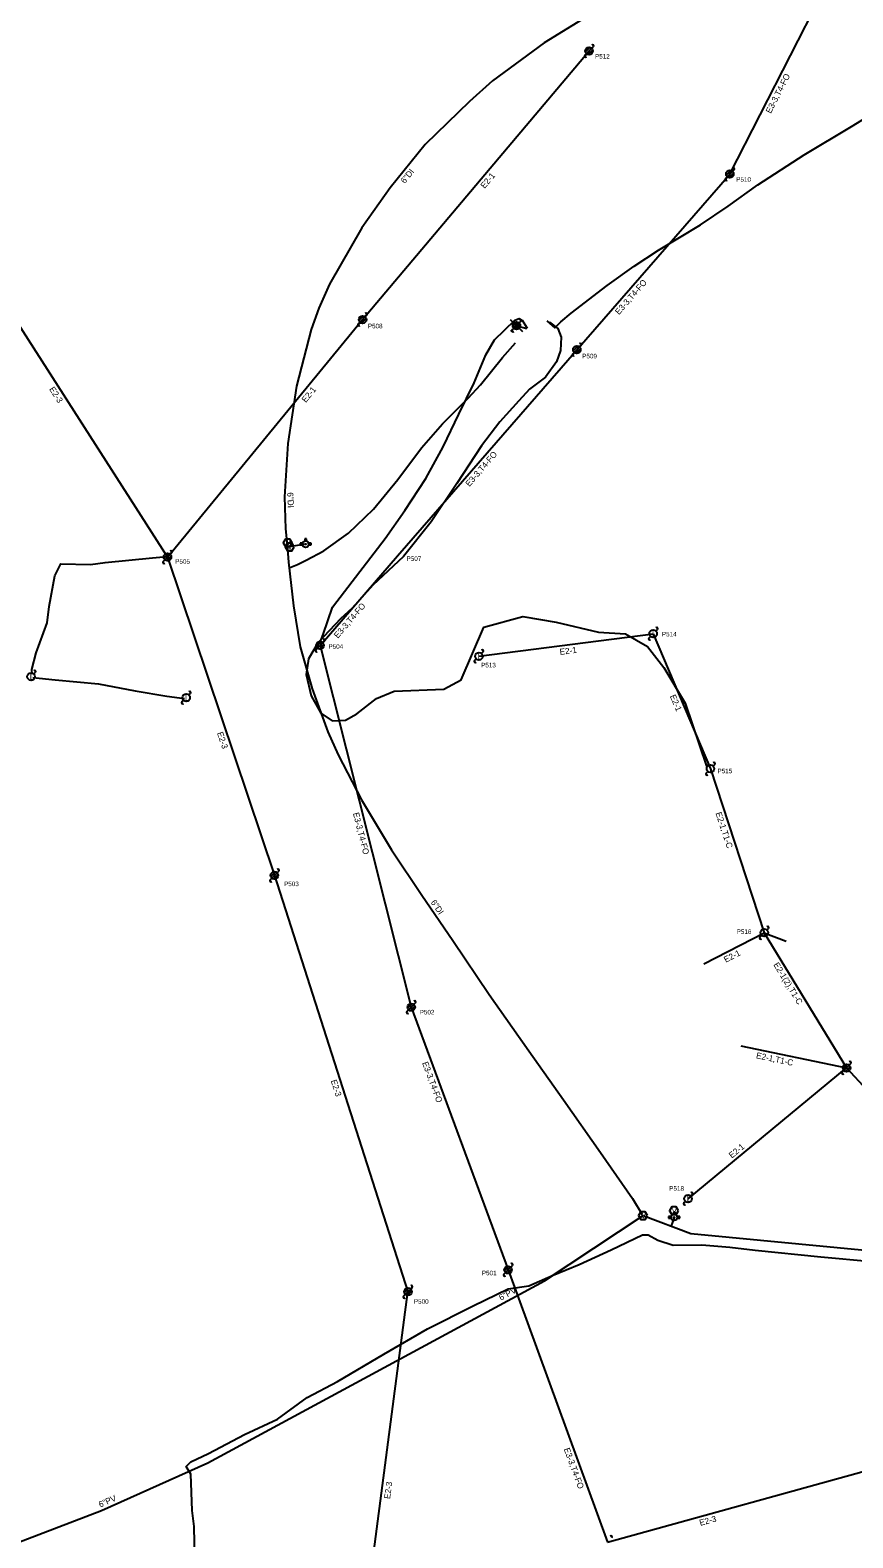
# Model space of a CAD drawing. Extents: x 1741604 to 1825760, y 1164229 to 1194908.
# Drawn here: x 1812735 to 1813275, y 1190349 to 1191338 of the extents above; entities that cross this region are included whole.
import ezdxf

# ---------------------------------------------------------------- set-up
doc = ezdxf.new("R2010")
doc.units = 0
for name, color, linetype in [('RD_EX_SU_Elec', 7, 'Continuous'), ('RD_EX_SU_H2O', 7, 'Continuous'), ('RD_EX_SU_Ovhd', 7, 'Continuous'), ('RD_EX_SU_Pole', 7, 'Continuous'), ('RD_EX_SU_Telecom', 7, 'Continuous'), ('RD_EX_SU_TX_H2O', 7, 'Continuous'), ('RD_EX_SU_TX_Pole', 7, 'Continuous')]:
    doc.layers.add(name, color=color, linetype=linetype)

# ---------------------------------------------------------------- blocks, each defined once
blk = doc.blocks.new('SUE_WV')
at = {"layer": 'RD_EX_SU_H2O'}
blk.add_lwpolyline([(2.89, 0), (1.44, 2.5), (-1.44, 2.5), (-2.89, 0), (-1.44, -2.5), (1.44, -2.5)], close=True, dxfattribs=at)
blk.add_text('V', height=3.75, dxfattribs=at).set_placement((-1.43, -1.88))
blk = doc.blocks.new('SUE_WFH')
at = {"layer": 'RD_EX_SU_H2O'}
for p, q in [((-2.01, 0.6), (-3.65, 0.6)), ((-3.65, 0.6), (-3.65, -0.45)), ((-0.48, 3.38), (-0.48, 2.04)), ((0.57, 3.38), (-0.48, 3.38)), ((0.57, 2.02), (0.57, 3.38)), ((3.7, 0.6), (2.01, 0.6)), ((3.7, -0.45), (3.7, 0.6)), ((-3.65, -0.45), (-2.05, -0.45)), ((2.05, -0.45), (3.7, -0.45))]:
    blk.add_line(p, q, dxfattribs=at)
for radius in [2.1, 0.263]:
    blk.add_circle((0, 0), radius, dxfattribs=at)
for start, end in [(163.3387, 192.31502), (74.24552, 103.21276), (347.68498, 16.6613)]:
    blk.add_arc((0, 0), 2.1, start, end, dxfattribs=at)
blk = doc.blocks.new('SUE_PGP')
at = {"layer": 'RD_EX_SU_Pole'}
for p, q in [((-1.06, 1.06), (-3.89, 3.89)), ((1.02, 1.12), (3.86, 3.96)), ((-1.11, -1.04), (-3.94, -3.87)), ((1.06, -1.06), (3.89, -3.89))]:
    blk.add_line(p, q, dxfattribs=at)
for points in [[(0, -2.12), (2.12, 0), (0, 2.12), (-2.12, 0)], [(0, -0.71), (0.71, 0), (0, 0.71), (-0.71, 0)]]:
    blk.add_lwpolyline(points, close=True, dxfattribs=at)
blk = doc.blocks.new('SUE_PP')
at = {"layer": 'RD_EX_SU_Pole'}
for p, q in [((-2.41, -0.65), (0.65, 2.41)), ((-1.77, -1.77), (1.77, 1.77)), ((-0.65, -2.41), (2.41, 0.65)), ((1.77, 1.77), (2.83, 2.83)), ((-2.83, -2.83), (-1.77, -1.77))]:
    blk.add_line(p, q, dxfattribs=at)
blk.add_circle((0, 0), 2.5, dxfattribs=at)
for centre, start, end in [((2.3, 3.36), 315, 135), ((-2.3, -3.36), 135, 315)]:
    blk.add_arc(centre, 0.75, start, end, dxfattribs=at)

msp = doc.modelspace()

# ---------------------------------------------------------------- linework, layer by layer
at = {"layer": 'RD_EX_SU_Elec'}
msp.add_line((1813054.62, 1191144.08), (1813061.12, 1191142.13), dxfattribs=at)
for points in [[(1813074.17, 1191147.22), (1813079.49, 1191142.73), (1813083.35, 1191146.53), (1813090.24, 1191152.3), (1813113.65, 1191170.54), (1813131.4, 1191183.04), (1813147.43, 1191193.7), (1813174.94, 1191210.3), (1813193.18, 1191222.5), (1813212.55, 1191236.51), (1813242.91, 1191256.26), (1813274.11, 1191274.83), (1813305.14, 1191293.76), (1813336.93, 1191314.29), (1813359.03, 1191328.39), (1813379.8, 1191342.76), (1813412.74, 1191364.15), (1813434.94, 1191378.63), (1813468.04, 1191399.22), (1813497.48, 1191419.37)], [(1812925.66, 1190935.15), (1812925.93, 1190937.58), (1812927.41, 1190941.39), (1812933.54, 1190959.29), (1812946.44, 1190976.3), (1812968.14, 1191004.38), (1812981.01, 1191022.74), (1812994.73, 1191043.72), (1813006.27, 1191064.6), (1813016.36, 1191085.94), (1813026.46, 1191106.6), (1813034.21, 1191124.91), (1813039.85, 1191134.84), (1813053.21, 1191147.79), (1813056.02, 1191148.81), (1813057.96, 1191147.72), (1813061.21, 1191142.37)], [(1812736.46, 1190915.41), (1812736.35, 1190918.55), (1812739.18, 1190929.32), (1812746.36, 1190949.03), (1812747.66, 1190959.89), (1812751.44, 1190980.01), (1812755.26, 1190987.79), (1812774.8, 1190987.36), (1812784.49, 1190988.75), (1812815.44, 1190991.73), (1812825.05, 1190992.69)], [(1812737.08, 1190913.27), (1812751.66, 1190911.7), (1812779.98, 1190909), (1812804.11, 1190904.54), (1812824.79, 1190901.05), (1812836.37, 1190899.52)]]:
    msp.add_lwpolyline(points, dxfattribs=at)
at = {"layer": 'RD_EX_SU_H2O'}
for p, q in [((1812914.82, 1191000.41), (1812903.88, 1190998.72)), ((1813072.65, 1190517.33), (1813137.28, 1190560.13)), ((1813157.74, 1190558.93), (1813155.64, 1190553.29)), ((1812851.86, 1190397.83), (1813072.65, 1190517.33)), ((1812782.06, 1190366.57), (1812851.86, 1190397.83)), ((1812695.37, 1190333.45), (1812782.06, 1190366.57))]:
    msp.add_line(p, q, dxfattribs=at)
for points in [[(1813137.28, 1190560.13), (1813168.69, 1190548.44), (1813548.05, 1190512.01), (1813709.49, 1190513.95), (1813790.71, 1190529.92), (1813879.02, 1190555.32), (1814045.36, 1190620.16), (1814170.98, 1190673.34), (1814340.25, 1190745.39), (1814593.33, 1190851.84), (1815112.4, 1191071.44), (1815429.86, 1191203.06), (1815618.35, 1191283.39), (1815883.49, 1191395.05), (1816374.39, 1191600.1)], [(1813105.92, 1191350.16), (1813072.42, 1191329.64), (1813038.59, 1191304.8), (1813023.51, 1191291.19), (1812994.25, 1191262.94), (1812971.3, 1191234.61), (1812952.71, 1191208.35), (1812931.66, 1191171.39), (1812924.71, 1191155.63), (1812919.62, 1191141.53), (1812910.03, 1191104.46), (1812904.33, 1191066.74), (1812901.98, 1191031.81), (1812902.81, 1191010.72), (1812903.77, 1190999.96), (1812904.72, 1190988.78), (1812907.9, 1190960.34), (1812912.27, 1190933.34), (1812920.22, 1190905.86), (1812930.45, 1190877.55), (1812937.38, 1190862.36), (1812952.67, 1190833.02), (1812972.35, 1190800.03), (1812992.14, 1190770.43), (1813012.42, 1190740.61), (1813036.45, 1190705.28), (1813062.33, 1190668.32), (1813085.13, 1190635.98), (1813109.45, 1190601.5), (1813130.33, 1190571.33), (1813136.74, 1190560.89)], [(1812905.12, 1190985.21), (1812910.61, 1190987.27), (1812916.33, 1190990.09), (1812927.91, 1190996.33), (1812944.09, 1191007.99), (1812960.51, 1191023.77), (1812976.45, 1191043.03), (1812991.91, 1191064), (1813005.62, 1191079.71), (1813022.46, 1191096.52), (1813030.66, 1191105.18), (1813045.15, 1191123.21), (1813053.52, 1191132.79)]]:
    msp.add_lwpolyline(points, dxfattribs=at)
at = {"layer": 'RD_EX_SU_Ovhd'}
for p, q in [((1813194.23, 1191243.55), (1813271.75, 1191395.47)), ((1812953.27, 1191148.1), (1813101.89, 1191324.36)), ((1813093.85, 1191128.3), (1813194.23, 1191243.55)), ((1812690.54, 1191202.47), (1812825.32, 1190992.22)), ((1812825.32, 1190992.22), (1812953.27, 1191148.1)), ((1812976.19, 1190993.08), (1813093.85, 1191128.3)), ((1812825.32, 1190992.22), (1812895.48, 1190783.31)), ((1812925.38, 1190934.22), (1812976.19, 1190993.08)), ((1813029.59, 1190927.16), (1813143.93, 1190941.93)), ((1813143.93, 1190941.93), (1813181.53, 1190853.31)), ((1812925.38, 1190934.22), (1812985.23, 1190696.86)), ((1813181.53, 1190853.31), (1813216.82, 1190745.69)), ((1812895.48, 1190783.31), (1812983.08, 1190510.11)), ((1813177.22, 1190725.31), (1813216.82, 1190745.69)), ((1813216.82, 1190745.69), (1813270.85, 1190657.03)), ((1813216.82, 1190745.69), (1813231.16, 1190740.26)), ((1812985.23, 1190696.86), (1813048.73, 1190524.49)), ((1813201.55, 1190671.56), (1813270.85, 1190657.03)), ((1813166.86, 1190571.19), (1813270.85, 1190657.03)), ((1813270.85, 1190657.03), (1813369.89, 1190548.84)), ((1813048.73, 1190524.49), (1813113.89, 1190345.79)), ((1812956.62, 1190307.89), (1812983.08, 1190510.11)), ((1813113.89, 1190345.79), (1813303.67, 1190398.31))]:
    msp.add_line(p, q, dxfattribs=at)
at = {"layer": 'RD_EX_SU_Pole'}
for p, q in [((1812950.86, 1191147.45), (1812953.92, 1191150.52)), ((1812951.5, 1191146.33), (1812955.04, 1191149.87)), ((1812955.04, 1191149.87), (1812956.1, 1191150.93)), ((1812950.44, 1191145.27), (1812951.5, 1191146.33)), ((1812952.62, 1191145.69), (1812955.69, 1191148.75)), ((1813051.46, 1191141.26), (1813052.52, 1191142.32)), ((1813056.05, 1191145.86), (1813057.11, 1191146.92)), ((1813091.44, 1191127.66), (1813094.5, 1191130.72)), ((1813092.08, 1191126.54), (1813095.62, 1191130.07)), ((1813095.62, 1191130.07), (1813096.68, 1191131.13)), ((1813091.02, 1191125.48), (1813092.08, 1191126.54)), ((1813093.2, 1191125.89), (1813096.26, 1191128.95)), ((1813145.7, 1190943.7), (1813146.76, 1190944.76)), ((1813141.1, 1190939.1), (1813142.16, 1190940.16)), ((1813026.76, 1190924.34), (1813027.82, 1190925.4)), ((1813031.36, 1190928.93), (1813032.42, 1190929.99)), ((1812737.6, 1190915.55), (1812738.66, 1190916.61)), ((1812839.35, 1190901.74), (1812840.41, 1190902.8)), ((1812834.75, 1190897.14), (1812835.82, 1190898.2)), ((1813183.3, 1190855.08), (1813184.36, 1190856.14)), ((1813178.7, 1190850.48), (1813179.76, 1190851.54)), ((1812893.07, 1190782.67), (1812896.13, 1190785.73)), ((1812893.71, 1190781.54), (1812897.25, 1190785.08)), ((1812894.83, 1190780.9), (1812897.9, 1190783.96)), ((1812897.25, 1190785.08), (1812898.31, 1190786.14)), ((1812892.65, 1190780.48), (1812893.71, 1190781.54)), ((1813218.59, 1190747.46), (1813219.65, 1190748.52)), ((1813214, 1190742.86), (1813215.06, 1190743.92)), ((1812982.4, 1190694.03), (1812983.46, 1190695.09)), ((1812982.81, 1190696.21), (1812985.87, 1190699.27)), ((1812983.46, 1190695.09), (1812986.99, 1190698.62)), ((1812984.58, 1190694.44), (1812987.64, 1190697.5)), ((1812986.99, 1190698.62), (1812988.06, 1190699.68)), ((1813268.02, 1190654.2), (1813269.08, 1190655.26)), ((1813268.43, 1190656.38), (1813271.49, 1190659.44)), ((1813269.08, 1190655.26), (1813272.62, 1190658.79)), ((1813270.2, 1190654.61), (1813273.26, 1190657.67)), ((1813272.62, 1190658.79), (1813273.68, 1190659.85)), ((1813164.03, 1190568.36), (1813165.09, 1190569.42)), ((1813168.63, 1190572.95), (1813169.69, 1190574.01)), ((1813046.31, 1190523.84), (1813049.38, 1190526.9)), ((1813050.5, 1190526.26), (1813051.56, 1190527.32)), ((1813045.9, 1190521.66), (1813046.96, 1190522.72)), ((1813046.96, 1190522.72), (1813050.5, 1190526.26)), ((1813048.08, 1190522.07), (1813051.14, 1190525.13)), ((1812980.25, 1190507.28), (1812981.31, 1190508.34)), ((1812980.66, 1190509.47), (1812983.73, 1190512.53)), ((1812981.31, 1190508.34), (1812984.85, 1190511.88)), ((1812982.43, 1190507.7), (1812985.49, 1190510.76)), ((1812984.85, 1190511.88), (1812985.91, 1190512.94))]:
    msp.add_line(p, q, dxfattribs=at)
for centre in [(1812953.27, 1191148.1), (1813054.28, 1191144.09), (1813093.85, 1191128.3), (1813143.93, 1190941.93), (1813029.59, 1190927.16), (1812735.83, 1190913.78), (1812837.58, 1190899.97), (1813181.53, 1190853.31), (1812895.48, 1190783.31), (1813216.82, 1190745.69), (1812985.23, 1190696.86), (1813270.85, 1190657.03), (1813166.86, 1190571.19), (1813048.73, 1190524.49), (1812983.08, 1190510.11)]:
    msp.add_circle(centre, 2.5, dxfattribs=at)
for centre, start, end in [((1812955.57, 1191151.46), 315, 135), ((1812950.97, 1191144.74), 135, 315), ((1813051.99, 1191140.73), 135, 315), ((1813056.58, 1191147.45), 315, 135), ((1813096.15, 1191131.66), 315, 135), ((1813091.55, 1191124.95), 135, 315), ((1813146.23, 1190945.29), 315, 135), ((1813141.63, 1190938.57), 135, 315), ((1813027.29, 1190923.81), 135, 315), ((1813031.89, 1190930.52), 315, 135), ((1812738.13, 1190917.14), 315, 135), ((1812839.88, 1190903.33), 315, 135), ((1812835.29, 1190896.61), 135, 315), ((1813183.83, 1190856.67), 315, 135), ((1813179.23, 1190849.95), 135, 315), ((1812897.78, 1190786.67), 315, 135), ((1812893.18, 1190779.95), 135, 315), ((1813219.12, 1190749.05), 315, 135), ((1813214.53, 1190742.33), 135, 315), ((1812987.52, 1190700.21), 315, 135), ((1812982.93, 1190693.5), 135, 315), ((1813273.15, 1190660.38), 315, 135), ((1813268.55, 1190653.67), 135, 315), ((1813164.56, 1190567.83), 135, 315), ((1813169.16, 1190574.54), 315, 135), ((1813051.03, 1190527.85), 315, 135), ((1813046.43, 1190521.13), 135, 315), ((1812980.78, 1190506.75), 135, 315), ((1812985.38, 1190513.47), 315, 135), ((1813116.18, 1190349.15), 315, 135)]:
    msp.add_arc(centre, 0.75, start, end, dxfattribs=at)
at = {"layer": 'RD_EX_SU_Telecom'}
for points in [[(1813075.9, 1191146.33), (1813081.3, 1191142.15), (1813083.55, 1191136.56), (1813083.24, 1191127.84), (1813080.5, 1191120.38), (1813073.28, 1191110.36), (1813062.89, 1191102.36), (1813055.91, 1191094.76), (1813043.44, 1191081), (1813031.41, 1191065.15), (1813015.23, 1191040.42), (1812998.32, 1191015.31), (1812980.22, 1190992.54), (1812959.95, 1190973.83), (1812946.46, 1190958.73), (1812938.9, 1190951.72), (1812924.12, 1190936.1), (1812917.86, 1190925.37), (1812916.27, 1190915.24), (1812919.56, 1190901.15), (1812926.01, 1190889.87), (1812933.35, 1190884.66), (1812942.01, 1190885.22), (1812949.54, 1190889.36), (1812962.53, 1190899.38), (1812974.09, 1190904.33), (1813006.52, 1190905.51), (1813018.03, 1190911.57), (1813032.81, 1190946.23), (1813058.51, 1190953.13), (1813080.19, 1190949.43), (1813108.15, 1190942.89), (1813125.68, 1190941.79), (1813140.18, 1190933.53), (1813150.93, 1190919.8), (1813164.87, 1190896.42), (1813178.87, 1190854.96), (1813180.8, 1190856.48)], [(1812843.31, 1190334.58), (1812842.75, 1190356.11), (1812841.42, 1190366.51), (1812840.59, 1190390.42), (1812837.48, 1190395.41), (1812840.66, 1190398.61), (1812852.12, 1190404.08), (1812875.87, 1190416.36), (1812897.57, 1190426.53), (1812916.88, 1190440.82), (1812936.9, 1190451.18), (1812967.26, 1190469.26), (1812995.95, 1190485.89), (1813025.82, 1190500.91), (1813048.78, 1190512.13), (1813062.4, 1190514.02), (1813078.27, 1190521.04), (1813095.35, 1190528.08), (1813116.42, 1190537.55), (1813136.88, 1190547.43), (1813140.56, 1190547.51), (1813147.1, 1190543.96), (1813157.02, 1190540.71), (1813175.86, 1190540.85), (1813194.32, 1190539.29), (1813210.75, 1190537.41), (1813253.99, 1190533.12), (1813320.8, 1190526.93)]]:
    msp.add_lwpolyline(points, dxfattribs=at)

# ---------------------------------------------------------------- block references
at = {"layer": 'RD_EX_SU_H2O'}
for name, p in [('SUE_WV', (1812904.19, 1191001.56)), ('SUE_WV', (1812905.45, 1190998.86)), ('SUE_WFH', (1812915.91, 1191000.71)), ('SUE_WV', (1813137.28, 1190560.13)), ('SUE_WFH', (1813157.74, 1190558.93)), ('SUE_WV', (1813157.57, 1190563.31))]:
    msp.add_blockref(name, p, dxfattribs=at)
at = {"layer": 'RD_EX_SU_Pole'}
for name, p in [('SUE_PP', (1813101.89, 1191324.36)), ('SUE_PP', (1813194.23, 1191243.55)), ('SUE_PGP', (1813054.28, 1191144.09)), ('SUE_PP', (1812825.32, 1190992.22)), ('SUE_PP', (1812925.38, 1190934.22))]:
    msp.add_blockref(name, p, dxfattribs=at)

# ---------------------------------------------------------------- texts
at = {"layer": 'RD_EX_SU_Ovhd'}
for s, rotation, p in [('E3-3,T4-FO', 62.96633, (1813221.1, 1191283.01)), ('E2-1', 49.86372, (1813033.33, 1191233.75)), ('E3-3,T4-FO', 48.94298, (1813121.52, 1191150.94)), ('E2-3', 302.66164, (1812747.54, 1191102.43)), ('E2-1', 50.62054, (1812916.02, 1191093.27)), ('E3-3,T4-FO', 48.97352, (1813023.37, 1191038.16)), ('E3-3,T4-FO', 49.19565, (1812937.09, 1190938.6)), ('E2-1', 7.35969, (1813082.85, 1190927.99)), ('E2-1', 292.99281, (1813154.79, 1190900.98)), ('E2-3', 288.56486, (1812857.77, 1190876.74)), ('E3-3,T4-FO', 284.15221, (1812946.96, 1190824.09)), ('E2-1,T1-C', 288.15656, (1813184.78, 1190824.14)), ('E2-1', 27.23403, (1813191.58, 1190725.95)), ('E2-1(2),T1-C', 301.35324, (1813222.64, 1190724.75)), ('E2-1,T1-C', 348.15334, (1813211.21, 1190663.4)), ('E3-3,T4-FO', 290.22448, (1812992.31, 1190660.26)), ('E2-3', 287.7778, (1812932.38, 1190648.59)), ('E2-1', 39.53964, (1813195.55, 1190597.46)), ('E3-3,T4-FO', 290.03299, (1813085.23, 1190406.87)), ('E2-3', 82.54595, (1812971.32, 1190373.96)), ('E2-3', 15.46791, (1813174.89, 1190356.45))]:
    msp.add_text(s, height=4, rotation=rotation, dxfattribs=at).set_placement(p)
at = {"layer": 'RD_EX_SU_Pole'}
for p in [(1813053.42, 1191142.09), (1813143.07, 1190939.93), (1813028.73, 1190925.16), (1812734.97, 1190911.78), (1812836.72, 1190897.97), (1813180.67, 1190851.31), (1813215.96, 1190743.69), (1813166, 1190569.19)]:
    msp.add_text('L', height=4, dxfattribs=at).set_placement(p)
at = {"layer": 'RD_EX_SU_TX_H2O'}
for s, rotation, p in [('6"DI', 50.98109, (1812980.99, 1191237.04)), ('6"DI', 272.24662, (1812903.87, 1191034.63)), ('6"DI', 304.21746, (1812997.82, 1190765.63)), ('6"PV', 28.42425, (1813044.09, 1190504.15)), ('6"PV', 24.12307, (1812781.2, 1190368.38))]:
    msp.add_text(s, height=4, rotation=rotation, dxfattribs=at).set_placement(p)
at = {"layer": 'RD_EX_SU_TX_Pole'}
for s, p in [('P512', (1813105.78, 1191319.32)), ('P510', (1813198.44, 1191238.52)), ('P508', (1812956.75, 1191142.35)), ('P509', (1813097.37, 1191122.63)), ('P507', (1812982.16, 1190989.71)), ('P505', (1812830.39, 1190987.83)), ('P514', (1813149.67, 1190940.15)), ('P504', (1812930.91, 1190932.02)), ('P513', (1813031.06, 1190919.83)), ('P515', (1813186.1, 1190850.37)), ('P503', (1812901.79, 1190776.28)), ('P516', (1813198.7, 1190744.92)), ('P502', (1812990.75, 1190692.09)), ('P518', (1813154.5, 1190576.43)), ('P501', (1813031.51, 1190520.92)), ('P500', (1812986.97, 1190502.22))]:
    msp.add_text(s, height=3, dxfattribs=at).set_placement(p)

doc.saveas('drawing.dxf')
